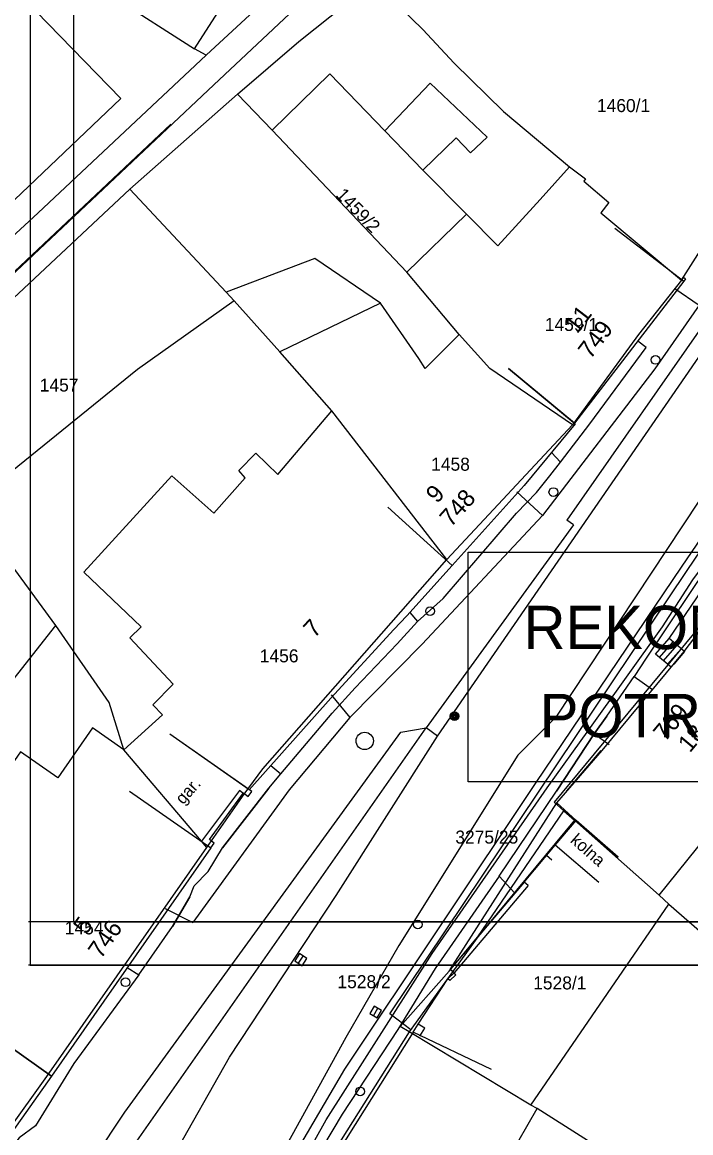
# Model space of a CAD drawing. Extents: x -601580 to 4, y -1204314 to 4.
# Drawn here: x -599729.1 to -599690.6, y -1204177.7 to -1204113.7 of the extents above; entities that cross this region are included whole.
import ezdxf

# ---------------------------------------------------------------- set-up
doc = ezdxf.new("R2010")
doc.units = 0
for name, color, linetype in [('00-INNOGY-NTL', 7, 'Continuous'), ('00-KN-HRANICE PARCEL', 7, 'Continuous'), ('00-KN-PARC. CISLA', 7, 'Continuous'), ('00-KN-VNITRNI KRESBA', 7, 'Continuous'), ('00-POLOHOPIS', 7, 'Continuous'), ('00-RAZÍTKO', 7, 'Continuous'), ('00-SITE KOM. KABEL', 7, 'Continuous'), ('00-VAK-KANAL-POTRUBI', 7, 'Continuous'), ('00-VAK-VODA-RAD IGIS', 7, 'Continuous'), ('11-REKONSTRUKCE VODOVOD', 7, 'Continuous'), ('11-REKONSTRUKCE VODOVOD POPIS', 7, 'Continuous'), ('Vrstva 25', 7, 'Continuous'), ('Vrstva 27', 7, 'Continuous'), ('Vrstva 28', 7, 'Continuous')]:
    doc.layers.add(name, color=color, linetype=linetype)

# ---------------------------------------------------------------- blocks, each defined once
blk = doc.blocks.new('6.30_40')
at = {"layer": 'Vrstva 27'}
blk.add_line((-0.25, 0.001), (0.25, -0.001), dxfattribs=at)
blk.add_lwpolyline([(-0.25, -0.25), (0.25, -0.25), (0.25, 0.25), (-0.25, 0.25)], close=True, dxfattribs=at)
blk = doc.blocks.new('6.30_42')
at = {"layer": 'Vrstva 27'}
blk.add_line((-0.25, 0), (0.25, 0), dxfattribs=at)
blk.add_lwpolyline([(-0.25, -0.25), (0.25, -0.25), (0.25, 0.25), (-0.25, 0.25)], close=True, dxfattribs=at)
blk = doc.blocks.new('6.14A_86')
at = {"layer": 'Vrstva 28'}
blk.add_circle((0, 0), 0.25, dxfattribs=at)
blk = doc.blocks.new('6.20_40')
at = {"layer": 'Vrstva 27'}
blk.add_circle((0, 0), 0.5, dxfattribs=at)
blk = doc.blocks.new('6.01A_954')
at = {"layer": 'Vrstva 25'}
for radius in [0.25, 0.2, 0.15, 0.1, 0.05]:
    blk.add_circle((0, 0), radius, dxfattribs=at)
blk = doc.blocks.new('6.14A_88')
at = {"layer": 'Vrstva 28'}
blk.add_circle((0, 0), 0.25, dxfattribs=at)
blk = doc.blocks.new('6.14A_90')
at = {"layer": 'Vrstva 28'}
blk.add_circle((0, 0), 0.25, dxfattribs=at)
blk = doc.blocks.new('6.14A_92')
at = {"layer": 'Vrstva 28'}
blk.add_circle((0, 0), 0.25, dxfattribs=at)
blk = doc.blocks.new('6.14A_206')
at = {"layer": 'Vrstva 28'}
blk.add_circle((0, 0), 0.25, dxfattribs=at)
blk = doc.blocks.new('6.14A_302')
at = {"layer": 'Vrstva 28'}
blk.add_circle((0, 0), 0.25, dxfattribs=at)

msp = doc.modelspace()

# ---------------------------------------------------------------- linework, layer by layer
for points in [[(-599518.659, -1204168.008), (-599518.659, -1204019.508), (-599728.659, -1204019.508), (-599728.659, -1204168.008)], [(-599521.159, -1204165.508), (-599521.159, -1204022.008), (-599726.159, -1204022.008), (-599726.159, -1204165.508)]]:
    msp.add_lwpolyline(points, close=True)
at = {"layer": '00-INNOGY-NTL'}
for p, q in [((-599691.54, -1204129.016), (-599690.14, -1204129.986)), ((-599700.64, -1204140.726), (-599699.15, -1204142.096)), ((-599711.32, -1204152.426), (-599710.24, -1204153.736)), ((-599696.49, -1204154.446), (-599695.31, -1204155.286)), ((-599720.88, -1204164.736), (-599719.28, -1204165.546))]:
    msp.add_line(p, q, dxfattribs=at)
for points in [[(-599729.43, -1204214.606), (-599728.86, -1204214.286), (-599728.65, -1204213.636), (-599727.61, -1204210.506), (-599726.77, -1204207.946), (-599726.34, -1204206.886), (-599723.29, -1204199.266), (-599722.52, -1204197.336), (-599717.28, -1204187.096), (-599715.16, -1204183.286), (-599711.61, -1204176.906), (-599705.5, -1204167.326), (-599698.88, -1204157.776), (-599696.49, -1204154.446), (-599692.24, -1204148.516), (-599690.49, -1204145.796), (-599689.94, -1204145.046), (-599681.46, -1204131.816), (-599680.08, -1204129.676), (-599676.05, -1204123.926), (-599673.73, -1204120.616), (-599671.11, -1204116.896), (-599670.55, -1204116.026), (-599666.85, -1204110.336)], [(-599673.73, -1204120.616), (-599680.85, -1204116.446), (-599688.76, -1204127.996), (-599690.14, -1204129.986), (-599692.69, -1204133.656), (-599699.15, -1204142.096), (-599706.08, -1204149.506), (-599710.24, -1204153.736), (-599713.74, -1204157.906), (-599719.28, -1204165.546)]]:
    msp.add_lwpolyline(points, dxfattribs=at)
at = {"layer": '00-KN-HRANICE PARCEL'}
for p, q in [((-599727.239, -1204110.056), (-599719.189, -1204115.216)), ((-599718.519, -1204115.576), (-599719.189, -1204115.216)), ((-599722.909, -1204123.296), (-599716.709, -1204117.826)), ((-599714.719, -1204119.896), (-599716.709, -1204117.826)), ((-599691.139, -1204128.546), (-599684.269, -1204117.636)), ((-599706.959, -1204128.086), (-599714.719, -1204119.896)), ((-599736.479, -1204135.986), (-599722.909, -1204123.296)), ((-599697.429, -1204136.866), (-599702.179, -1204133.636)), ((-599704.669, -1204144.626), (-599697.429, -1204136.866)), ((-599727.179, -1204148.436), (-599731.719, -1204142.246)), ((-599698.489, -1204158.606), (-599697.919, -1204159.106)), ((-599702.869, -1204166.376), (-599697.919, -1204159.106)), ((-599697.919, -1204159.106), (-599697.309, -1204159.646)), ((-599697.309, -1204159.646), (-599702.869, -1204166.376)), ((-599727.699, -1204174.406), (-599718.489, -1204161.216)), ((-599702.869, -1204166.376), (-599706.839, -1204171.846)), ((-599706.839, -1204171.846), (-599707.359, -1204171.536)), ((-599706.839, -1204171.846), (-599715.759, -1204186.016)), ((-599729.969, -1204177.586), (-599727.699, -1204174.406))]:
    msp.add_line(p, q, dxfattribs=at)
for points in [[(-599719.189, -1204115.216), (-599709.459, -1204100.036), (-599706.239, -1204102.076), (-599702.999, -1204097.036), (-599700.489, -1204098.646), (-599693.529, -1204087.766), (-599708.169, -1204078.466), (-599705.049, -1204073.146)], [(-599718.519, -1204115.576), (-599713.519, -1204110.936), (-599709.309, -1204107.996), (-599705.029, -1204105.376), (-599697.099, -1204100.876), (-599689.999, -1204096.046)], [(-599743.169, -1204132.656), (-599743.949, -1204133.396), (-599746.259, -1204131.026), (-599745.579, -1204130.326), (-599748.659, -1204127.076), (-599731.139, -1204110.156), (-599723.439, -1204118.066), (-599740.999, -1204134.806), (-599743.169, -1204132.656)], [(-599716.709, -1204117.826), (-599713.179, -1204114.786), (-599708.669, -1204111.186)], [(-599707.339, -1204112.856), (-599706.049, -1204114.096), (-599704.239, -1204116.046), (-599701.399, -1204118.826), (-599697.589, -1204122.006), (-599696.669, -1204122.706), (-599696.779, -1204122.836), (-599695.329, -1204124.066), (-599695.799, -1204124.656), (-599691.139, -1204128.546)], [(-599741.709, -1204137.226), (-599741.089, -1204136.576), (-599728.199, -1204124.666), (-599718.519, -1204115.576)], [(-599714.719, -1204119.896), (-599711.409, -1204116.656), (-599708.229, -1204119.946), (-599706.049, -1204122.196), (-599703.529, -1204124.736), (-599706.959, -1204128.086)], [(-599716.909, -1204129.736), (-599717.369, -1204129.236), (-599722.909, -1204123.296)], [(-599702.179, -1204133.636), (-599703.949, -1204131.666), (-599706.959, -1204128.086)], [(-599691.139, -1204128.546), (-599693.619, -1204131.676), (-599697.429, -1204136.866)], [(-599716.909, -1204129.736), (-599722.479, -1204133.686), (-599732.229, -1204141.576)], [(-599704.669, -1204144.626), (-599711.279, -1204136.066), (-599714.289, -1204132.676), (-599716.909, -1204129.736)], [(-599718.489, -1204161.216), (-599716.339, -1204158.146), (-599715.249, -1204156.696), (-599704.669, -1204144.626)], [(-599687.199, -1204147.596), (-599688.609, -1204146.676), (-599698.489, -1204158.606)], [(-599746.849, -1204172.856), (-599740.969, -1204165.936), (-599727.179, -1204148.436)], [(-599723.269, -1204155.586), (-599724.099, -1204152.876), (-599727.179, -1204148.436)], [(-599723.269, -1204155.586), (-599725.059, -1204154.336), (-599727.059, -1204157.206), (-599729.209, -1204155.706), (-599734.379, -1204163.116), (-599731.549, -1204165.036), (-599735.119, -1204169.266)], [(-599718.489, -1204161.216), (-599718.789, -1204160.866), (-599723.269, -1204155.586)], [(-599697.309, -1204159.646), (-599692.429, -1204163.966), (-599691.869, -1204164.476), (-599684.849, -1204170.586), (-599683.669, -1204171.796), (-599682.849, -1204172.416), (-599680.249, -1204173.606)], [(-599707.359, -1204171.536), (-599704.529, -1204168.336), (-599702.869, -1204166.376)], [(-599686.169, -1204184.716), (-599687.069, -1204184.146), (-599691.609, -1204181.256), (-599699.459, -1204176.266), (-599699.829, -1204176.056), (-599706.839, -1204171.846)]]:
    msp.add_lwpolyline(points, dxfattribs=at)
at = {"layer": '00-KN-VNITRNI KRESBA'}
for p, q in [((-599705.619, -1204117.196), (-599708.229, -1204119.946)), ((-599702.349, -1204120.306), (-599705.619, -1204117.196)), ((-599706.049, -1204122.196), (-599704.119, -1204120.336)), ((-599704.119, -1204120.336), (-599703.299, -1204121.196)), ((-599703.299, -1204121.196), (-599702.349, -1204120.306)), ((-599697.589, -1204122.006), (-599699.279, -1204123.886)), ((-599699.279, -1204123.886), (-599701.719, -1204126.566)), ((-599701.719, -1204126.566), (-599703.529, -1204124.736)), ((-599712.259, -1204127.286), (-599717.369, -1204129.236)), ((-599708.479, -1204129.866), (-599712.259, -1204127.286)), ((-599708.479, -1204129.866), (-599714.289, -1204132.676)), ((-599706.269, -1204133.056), (-599708.479, -1204129.866)), ((-599703.949, -1204131.666), (-599705.909, -1204133.636)), ((-599705.909, -1204133.636), (-599706.269, -1204133.056)), ((-599714.389, -1204139.726), (-599711.279, -1204136.066)), ((-599716.639, -1204139.506), (-599715.659, -1204138.496)), ((-599715.659, -1204138.496), (-599714.389, -1204139.726)), ((-599716.279, -1204139.926), (-599716.639, -1204139.506)), ((-599725.569, -1204145.366), (-599720.499, -1204139.816)), ((-599720.499, -1204139.816), (-599718.089, -1204141.966)), ((-599718.089, -1204141.966), (-599716.279, -1204139.926)), ((-599722.259, -1204148.506), (-599725.569, -1204145.366)), ((-599722.909, -1204149.146), (-599722.259, -1204148.506)), ((-599720.419, -1204151.806), (-599722.909, -1204149.146)), ((-599721.599, -1204152.996), (-599720.419, -1204151.806)), ((-599721.029, -1204153.576), (-599721.599, -1204152.996)), ((-599723.269, -1204155.586), (-599721.029, -1204153.576)), ((-599692.429, -1204163.966), (-599686.349, -1204156.386)), ((-599716.599, -1204157.936), (-599718.789, -1204160.866)), ((-599716.339, -1204158.146), (-599716.599, -1204157.936)), ((-599699.829, -1204176.056), (-599691.869, -1204164.476)), ((-599702.659, -1204181.826), (-599699.459, -1204176.266))]:
    msp.add_line(p, q, dxfattribs=at)
at = {"layer": '00-POLOHOPIS'}
for p, q in [((-599680.591, -1204117.773), (-599697.745, -1204142.358)), ((-599705.207, -1204154.806), (-599679.979, -1204118.2)), ((-599691.113, -1204145.011), (-599679.203, -1204127.46)), ((-599691.032, -1204128.363), (-599691.135, -1204128.498)), ((-599691.032, -1204128.363), (-599690.913, -1204128.454)), ((-599690.913, -1204128.454), (-599691.016, -1204128.589)), ((-599697.264, -1204136.818), (-599700.215, -1204140.362)), ((-599697.36, -1204142.627), (-599705.854, -1204154.336)), ((-599697.36, -1204142.627), (-599697.745, -1204142.358)), ((-599699.554, -1204157.539), (-599691.113, -1204145.011)), ((-599691.851, -1204149.179), (-599689.65, -1204145.946)), ((-599692.644, -1204150.079), (-599691.851, -1204149.179)), ((-599690.984, -1204149.923), (-599691.851, -1204149.179)), ((-599692.413, -1204150.271), (-599691.625, -1204149.377)), ((-599692.182, -1204150.462), (-599691.4, -1204149.575)), ((-599691.951, -1204150.654), (-599691.175, -1204149.773)), ((-599691.736, -1204150.832), (-599692.644, -1204150.079)), ((-599690.984, -1204149.923), (-599691.599, -1204150.666)), ((-599730.792, -1204189.94), (-599705.854, -1204154.336)), ((-599707.304, -1204154.573), (-599705.854, -1204154.336)), ((-599705.207, -1204154.806), (-599705.854, -1204154.336)), ((-599723.21, -1204176.467), (-599707.304, -1204154.573)), ((-599711.026, -1204163.979), (-599705.207, -1204154.806)), ((-599697.748, -1204157.957), (-599695.783, -1204155.624)), ((-599710.537, -1204173.99), (-599699.554, -1204157.539)), ((-599704.473, -1204168.253), (-599698.328, -1204158.646)), ((-599698.618, -1204161.942), (-599698.924, -1204161.685)), ((-599700.212, -1204163.215), (-599704.473, -1204168.253)), ((-599699.983, -1204163.409), (-599700.212, -1204163.215)), ((-599699.983, -1204163.409), (-599704.244, -1204168.447)), ((-599717.186, -1204173.293), (-599711.026, -1204163.979)), ((-599704.601, -1204168.782), (-599704.244, -1204168.447)), ((-599704.244, -1204168.447), (-599704.473, -1204168.253)), ((-599704.141, -1204168.556), (-599704.244, -1204168.447)), ((-599706.311, -1204171.39), (-599704.601, -1204168.782)), ((-599704.498, -1204168.891), (-599704.601, -1204168.782)), ((-599704.498, -1204168.891), (-599704.141, -1204168.556)), ((-599706.6, -1204171.861), (-599706.311, -1204171.39)), ((-599705.927, -1204171.625), (-599706.311, -1204171.39)), ((-599706.216, -1204172.096), (-599705.927, -1204171.625)), ((-599723.422, -1204184.333), (-599717.186, -1204173.293)), ((-599717.145, -1204185.245), (-599710.537, -1204173.99)), ((-599742.837, -1204206.102), (-599723.21, -1204176.467))]:
    msp.add_line(p, q, dxfattribs=at)
for points in [[(-599694.984, -1204125.547), (-599691.016, -1204128.589), (-599697.301, -1204136.786), (-599701.106, -1204133.619)], [(-599701.106, -1204133.619), (-599697.264, -1204136.818), (-599700.215, -1204140.362), (-599704.352, -1204144.971), (-599708.067, -1204141.624)], [(-599708.067, -1204141.624), (-599704.352, -1204144.971), (-599706.974, -1204147.881), (-599707.715, -1204148.657), (-599711.348, -1204152.613), (-599716.038, -1204157.893), (-599720.623, -1204154.7)], [(-599694.795, -1204161.775), (-599697.211, -1204159.66), (-599698.328, -1204158.646), (-599695.722, -1204155.638), (-599690.993, -1204149.935), (-599688.594, -1204146.779), (-599684.386, -1204149.86)], [(-599722.929, -1204157.968), (-599718.248, -1204161.231), (-599718.054, -1204160.964), (-599718.321, -1204160.77), (-599716.369, -1204158.081), (-599716.102, -1204158.275), (-599715.896, -1204157.992), (-599720.623, -1204154.7)], [(-599722.929, -1204157.968), (-599718.248, -1204161.231), (-599727.427, -1204174.399), (-599731.506, -1204171.508)], [(-599695.914, -1204163.229), (-599698.429, -1204161.096), (-599697.211, -1204159.66), (-599694.795, -1204161.775)], [(-599700.212, -1204163.215), (-599698.429, -1204161.096)], [(-599731.506, -1204171.508), (-599727.427, -1204174.399), (-599735.955, -1204186.43), (-599740.034, -1204183.538)], [(-599702.086, -1204174.011), (-599706.6, -1204171.861), (-599715.684, -1204186.311), (-599715.684, -1204186.311), (-599707.877, -1204190.842)]]:
    msp.add_lwpolyline(points, dxfattribs=at)
at = {"layer": '00-RAZÍTKO'}
for points in [[(-599728.76, -1204019.508), (-599518.659, -1204019.508), (-599518.659, -1204168.008), (-599728.76, -1204168.008)], [(-599728.76, -1204022.008), (-599521.159, -1204022.008), (-599521.159, -1204165.508), (-599728.76, -1204165.508)]]:
    msp.add_lwpolyline(points, dxfattribs=at)
at = {"layer": '00-SITE KOM. KABEL'}
for points in [[(-599706.729, -1204171.726), (-599707.939, -1204170.796), (-599690.829, -1204145.256), (-599680.939, -1204130.676), (-599669.219, -1204113.236), (-599666.739, -1204109.486), (-599666.509, -1204107.356), (-599660.459, -1204098.156), (-599658.139, -1204095.976), (-599651.239, -1204085.636), (-599633.359, -1204060.796), (-599621.999, -1204045.836)], [(-599698.109, -1204139.016), (-599696.429, -1204136.806), (-599693.179, -1204132.416), (-599693.669, -1204132.046)], [(-599706.359, -1204148.206), (-599704.879, -1204146.876), (-599700.649, -1204141.966), (-599699.499, -1204140.766), (-599698.739, -1204139.806), (-599698.109, -1204139.016)], [(-599698.639, -1204138.466), (-599698.109, -1204139.016)], [(-599699.499, -1204140.766), (-599700.649, -1204141.966)], [(-599688.559, -1204143.446), (-599690.419, -1204146.186), (-599692.049, -1204148.626), (-599693.179, -1204150.306), (-599693.869, -1204151.366)], [(-599706.789, -1204147.676), (-599706.359, -1204148.206)], [(-599714.219, -1204156.976), (-599711.269, -1204153.486), (-599709.939, -1204152.016), (-599707.529, -1204149.486), (-599706.359, -1204148.206)], [(-599706.359, -1204148.206), (-599707.529, -1204149.486)], [(-599692.049, -1204148.626), (-599693.179, -1204150.306)], [(-599701.649, -1204162.876), (-599698.349, -1204157.976), (-599696.169, -1204154.676), (-599695.439, -1204153.656), (-599693.869, -1204151.366)], [(-599693.869, -1204151.366), (-599692.809, -1204152.126)], [(-599709.939, -1204152.016), (-599711.269, -1204153.486)], [(-599695.439, -1204153.656), (-599696.169, -1204154.676)], [(-599696.169, -1204154.676), (-599698.349, -1204157.976)], [(-599714.799, -1204156.506), (-599714.219, -1204156.976)], [(-599722.399, -1204168.556), (-599720.469, -1204165.766), (-599719.459, -1204164.066), (-599719.219, -1204163.426), (-599718.399, -1204162.606), (-599717.589, -1204161.236), (-599714.919, -1204157.796), (-599714.219, -1204156.976)], [(-599714.919, -1204157.796), (-599717.589, -1204161.236)], [(-599701.649, -1204162.876), (-599705.329, -1204168.196), (-599707.489, -1204171.696), (-599710.699, -1204176.576), (-599713.009, -1204180.486)], [(-599700.739, -1204163.846), (-599701.649, -1204162.876)], [(-599719.459, -1204164.066), (-599720.469, -1204165.766)], [(-599723.079, -1204168.136), (-599722.399, -1204168.556)], [(-599705.329, -1204168.196), (-599707.489, -1204171.696)], [(-599722.399, -1204168.556), (-599726.139, -1204173.656), (-599728.359, -1204177.246), (-599729.299, -1204177.946), (-599730.609, -1204179.636), (-599731.249, -1204180.876), (-599735.409, -1204186.626), (-599737.249, -1204189.686), (-599740.519, -1204195.946)], [(-599726.139, -1204173.656), (-599728.359, -1204177.246)]]:
    msp.add_lwpolyline(points, dxfattribs=at)
at = {"layer": '00-VAK-KANAL-POTRUBI'}
for points in [[(-599712.785, -1204112.294), (-599718.086, -1204117.292), (-599730.131, -1204128.65), (-599738.867, -1204136.888), (-599749.336, -1204148.716), (-599755.579, -1204156.546), (-599780.096, -1204187.297), (-599781.255, -1204188.751)], [(-599720.551, -1204119.552), (-599738.9, -1204136.833), (-599749.422, -1204148.631), (-599781.252, -1204188.713), (-599781.255, -1204188.751)]]:
    msp.add_lwpolyline(points, dxfattribs=at)
at = {"layer": '00-VAK-VODA-RAD IGIS'}
msp.add_lwpolyline([(-599663.464, -1204100.29), (-599666.159, -1204104.046), (-599667.489, -1204106.926), (-599668.449, -1204108.516), (-599680.109, -1204126.116), (-599689.249, -1204139.906), (-599698.389, -1204153.706), (-599700.579, -1204155.896), (-599707.429, -1204166.866), (-599710.479, -1204172.166), (-599714.109, -1204178.746), (-599718.152, -1204186.058), (-599724.869, -1204198.496), (-599733.519, -1204221.536), (-599739.97, -1204237.6), (-599742.235, -1204243.238), (-599747.709, -1204252.896), (-599757.019, -1204268.226), (-599762.359, -1204276.456), (-599765.698, -1204280.085), (-599766.059, -1204280.726)], dxfattribs=at)
at = {"layer": '11-REKONSTRUKCE VODOVOD'}
msp.add_lwpolyline([(-599703.431, -1204144.208), (-599630.862, -1204144.208), (-599630.862, -1204157.43), (-599703.431, -1204157.43)], close=True, dxfattribs=at)
at = {"layer": '11-REKONSTRUKCE VODOVOD POPIS'}
msp.add_lwpolyline([(-599703.431, -1204144.208), (-599630.862, -1204144.208), (-599630.862, -1204157.43), (-599703.431, -1204157.43)], close=True, dxfattribs=at)

# ---------------------------------------------------------------- block references
at = {"layer": '00-POLOHOPIS', "rotation": -90.00000000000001}
for name, p in [('6.14A_88', (-599692.649, -1204133.135)), ('6.14A_90', (-599698.529, -1204140.746)), ('6.14A_92', (-599705.631, -1204147.611)), ('6.14A_206', (-599723.161, -1204168.986))]:
    msp.add_blockref(name, p, dxfattribs=at)
at = {"layer": '00-POLOHOPIS'}
for name, p, xscale, yscale, rotation in [('6.01A_954', (-599704.22, -1204153.654), 0.99999916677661, 0.99999916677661, 59.52314605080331), ('6.20_40', (-599709.393, -1204155.08), 0.99999916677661, 0.99999916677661, 59.52314605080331), ('6.14A_302', (-599706.33, -1204165.659), 1.00000010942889, 1.0000001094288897, 147.91820085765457), ('6.30_40', (-599713.073, -1204167.683), 1.00000166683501, 1.0000016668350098, 56.90111451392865), ('6.30_42', (-599708.763, -1204170.699), 0.99999916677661, 0.99999916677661, 59.52314605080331), ('6.14A_86', (-599709.658, -1204175.271), 0.99999916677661, 0.99999916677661, 59.52314605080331)]:
    msp.add_blockref(name, p, dxfattribs=dict(at, xscale=xscale, yscale=yscale, rotation=rotation))

# ---------------------------------------------------------------- texts
at = {"layer": '00-KN-PARC. CISLA'}
for s, p in [('1460/1', (-599696.019, -1204118.856)), ('1459/1', (-599699.019, -1204131.466)), ('1457', (-599728.105, -1204134.956)), ('1458', (-599705.565, -1204139.516)), ('1456', (-599715.435, -1204150.556)), ('3275/25', (-599704.174, -1204160.996)), ('1454', (-599726.665, -1204166.226)), ('1528/2', (-599710.962, -1204169.326)), ('1528/1', (-599699.689, -1204169.396))]:
    msp.add_text(s, height=0.75, dxfattribs=at).set_placement(p)
msp.add_text('1459/2', height=0.75, rotation=314, dxfattribs=at).set_placement((-599711.099, -1204123.671))
at = {"layer": '00-POLOHOPIS'}
for s, height, rotation, p in [('11', 1, 52.52127, (-599697.159, -1204131.67)), ('749', 1, 52.52127, (-599696.393, -1204133.136)), ('9', 1, 48.08911, (-599705.22, -1204141.445)), ('748', 1, 48.08911, (-599704.426, -1204142.807)), ('7', 1, 47.43713, (-599712.285, -1204149.197)), ('769', 1, 50.33405, (-599692.093, -1204155.177)), ('18', 1, 50.33405, (-599690.666, -1204155.807)), ('gar.', 0.7, 48.34021, (-599719.847, -1204158.785)), ('kolna', 0.7, 318.53764, (-599697.6, -1204160.881)), ('5', 1, 55.12086, (-599725.427, -1204166.282)), ('746', 1, 55.12086, (-599724.577, -1204167.686))]:
    msp.add_text(s, height=height, rotation=rotation, dxfattribs=at).set_placement(p)
at = {"layer": '11-REKONSTRUKCE VODOVOD'}
for s, p in [('REKONSTRUKCE VODOVODU 26,60 m', (-599700.241, -1204149.796)), (' POTRUBÍ PE DN100 ', (-599700.241, -1204154.874))]:
    msp.add_text(s, height=2.5, dxfattribs=at).set_placement(p)

doc.saveas('drawing.dxf')
